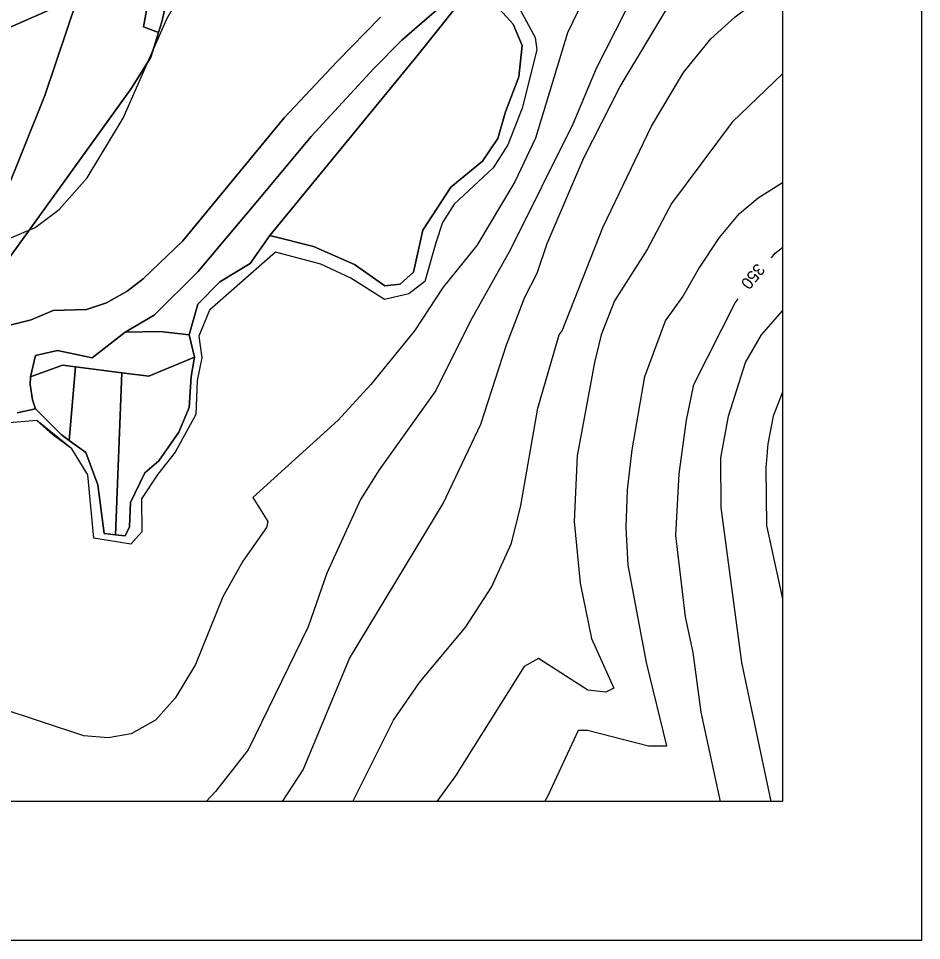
# Model space of a CAD drawing. Extents: x -510989 to -501240, y -1184665 to -1176098.
# Drawn here: x -501694.8 to -501240.2, y -1184460 to -1183995.8 of the extents above; entities that cross this region are included whole.
import ezdxf

# ---------------------------------------------------------------- set-up
doc = ezdxf.new("R2010")
doc.units = 0
for name, color, linetype in [('orna_puda', 7, 'Continuous'), ('ostatni_plocha_x_draha', 7, 'Continuous'), ('popis', 7, 'Continuous'), ('rozpiska', 7, 'Continuous'), ('trvaly_travni_porost', 7, 'Continuous'), ('vodni_plocha_x_vodni_tok_v_koryt_prir_n_upr', 7, 'Continuous'), ('vrstevnice_01', 7, 'Continuous'), ('vrstevnice_02', 7, 'Continuous'), ('vrstevnice_04', 7, 'Continuous')]:
    doc.layers.add(name, color=color, linetype=linetype)

msp = doc.modelspace()

# ---------------------------------------------------------------- linework, layer by layer
at = {"layer": 'orna_puda'}
msp.add_lwpolyline([(-501512.55, -1183995.12), (-501534.61, -1184017.6), (-501561.07, -1184045.86), (-501612.09, -1184107.75), (-501632.04, -1184126.86), (-501640.1, -1184133.08), (-501650.4, -1184138.89), (-501660.56, -1184142.34), (-501677.32, -1184142.83), (-501688.38, -1184147.53), (-501707.95, -1184152.37), (-501728.19, -1184147.52), (-501731.54, -1184150.05), (-501738.69, -1184147.66), (-501728.56, -1184144.08), (-501706.37, -1184125.67), (-501637.9, -1184030.79), (-501628.17, -1184015.32), (-501624.3, -1184002.75), (-501622.66, -1183997.39), (-501612.32, -1183952.6)], dxfattribs=at)
for points in [[(-501612.32, -1183952.6), (-501622.66, -1183997.39), (-501624.3, -1184002.75), (-501631.88, -1183999.91), (-501624.62, -1183960.62), (-501615.08, -1183954.85)], [(-501464.7, -1183977.67), (-501445.71, -1183998.59), (-501441.23, -1184009.29), (-501442.97, -1184025.07), (-501449.69, -1184042.78), (-501453.46, -1184056.27), (-501461.22, -1184067.58), (-501477.17, -1184080.78), (-501491.19, -1184102.41), (-501495.99, -1184123.43), (-501502.72, -1184129.59), (-501510.34, -1184130.29), (-501525.6, -1184119.62), (-501546.27, -1184110.6), (-501568.32, -1184105.06), (-501494.17, -1184014.62)], [(-501664.91, -1183985.01), (-501681.56, -1184034.59), (-501702.32, -1184086.41), (-501722.03, -1184129.14), (-501735.56, -1184129.64), (-501753.3, -1184131.89), (-501747.55, -1184098.48), (-501737.14, -1184058.29), (-501725.5, -1184011.71)], [(-501629.19, -1184175.85), (-501606.21, -1184166.31), (-501607.79, -1184175.98), (-501608.86, -1184191.6), (-501614.12, -1184203.97), (-501624.11, -1184218.42), (-501631.17, -1184224.53), (-501638.45, -1184239.5), (-501638.95, -1184251.68), (-501641.04, -1184256.31), (-501645.92, -1184255.77), (-501642.73, -1184174.11)], [(-501672.55, -1184170.26), (-501666.07, -1184171.1), (-501669.26, -1184208.24), (-501673.38, -1184205.25), (-501686.2, -1184192.28), (-501687.81, -1184187.75), (-501688.92, -1184180.06), (-501688.75, -1184176.23)], [(-501666.07, -1184171.1), (-501642.73, -1184174.11), (-501645.92, -1184255.77), (-501651.57, -1184255.14), (-501654.82, -1184230.52), (-501660.84, -1184214.35), (-501669.26, -1184208.24)]]:
    msp.add_lwpolyline(points, close=True, dxfattribs=at)
at = {"layer": 'ostatni_plocha_x_draha'}
msp.add_lwpolyline([(-501664.91, -1183985.01), (-501725.5, -1184011.71), (-501735.92, -1184015.8), (-501756.19, -1184021.57), (-501777.62, -1184027.66), (-501796.28, -1184026.35), (-501817.33, -1184025.47), (-501837.44, -1184019.49), (-501848.27, -1184040.14), (-501854.1, -1184015.89), (-501894.48, -1184008.62), (-501897.73, -1184020.9), (-501911.35, -1184013.65), (-501926.09, -1183995.79), (-501924.39, -1183992.84)], dxfattribs=at)
at = {"layer": 'popis'}
msp.add_lwpolyline([(-501442.37, -1183991.15), (-501434.74, -1184005.42), (-501433.91, -1184011.62), (-501441.25, -1184040.89), (-501448.43, -1184059.31), (-501455.91, -1184070.91), (-501475.4, -1184089.29), (-501481.35, -1184098.5), (-501484.72, -1184108.73), (-501490.24, -1184128.12), (-501498.31, -1184134.34), (-501510.57, -1184137.27), (-501527.46, -1184126.57), (-501542.53, -1184119.5), (-501565.43, -1184113.46), (-501598.56, -1184142.62), (-501603.96, -1184155.65), (-501602.48, -1184166.68), (-501604.88, -1184178.11), (-501605.58, -1184195.15), (-501615.91, -1184214.08), (-501624.7, -1184225.14), (-501632.88, -1184237.62), (-501632.61, -1184254.22), (-501638.24, -1184260.44), (-501656.8, -1184257.46), (-501659.89, -1184225.51), (-501667.92, -1184212.44), (-501685.55, -1184198.22), (-501705.56, -1184199.8)], dxfattribs=at)
at = {"layer": 'rozpiska'}
for points in [[(-501240.19, -1178160), (-501240.19, -1184460), (-507180.19, -1184460), (-507180.19, -1178160)], [(-507110.19, -1184390), (-507110.19, -1178230), (-501310.19, -1178230), (-501310.19, -1184390)]]:
    msp.add_lwpolyline(points, close=True, dxfattribs=at)
at = {"layer": 'trvaly_travni_porost'}
for points in [[(-501624.62, -1183960.62), (-501631.88, -1183999.91), (-501624.3, -1184002.75), (-501628.17, -1184015.32), (-501637.9, -1184030.79), (-501706.37, -1184125.67), (-501722.03, -1184129.14), (-501702.32, -1184086.41), (-501681.56, -1184034.59), (-501664.91, -1183985.01)], [(-501463.08, -1183970.24), (-501464.7, -1183977.67), (-501494.17, -1184014.62), (-501568.32, -1184105.06), (-501578.13, -1184119.1), (-501593.44, -1184128.39), (-501604.5, -1184139.67), (-501608.91, -1184155.1), (-501623.51, -1184153.4), (-501641.1, -1184153.63), (-501626.41, -1184145.06), (-501604.42, -1184123.24), (-501574.28, -1184087.35), (-501547.37, -1184055.26), (-501515.98, -1184021), (-501501.76, -1184006.63), (-501472.92, -1183981.46)], [(-501623.51, -1184153.4), (-501608.91, -1184155.1), (-501606.21, -1184166.31), (-501629.19, -1184175.85), (-501642.73, -1184174.11), (-501666.07, -1184171.1), (-501672.55, -1184170.26), (-501688.75, -1184176.23), (-501686.24, -1184165.52), (-501675.22, -1184162.88), (-501657.77, -1184166.57), (-501641.1, -1184153.63)]]:
    msp.add_lwpolyline(points, close=True, dxfattribs=at)
at = {"layer": 'vodni_plocha_x_vodni_tok_v_koryt_prir_n_upr'}
for points in [[(-501695.38, -1184194.27), (-501686.2, -1184192.28), (-501673.38, -1184205.25), (-501669.26, -1184208.24), (-501660.84, -1184214.35), (-501654.82, -1184230.52), (-501651.57, -1184255.14), (-501645.92, -1184255.77), (-501641.04, -1184256.31), (-501638.95, -1184251.68), (-501638.45, -1184239.5), (-501631.17, -1184224.53), (-501624.11, -1184218.42), (-501614.12, -1184203.97), (-501608.86, -1184191.6), (-501607.79, -1184175.98), (-501606.21, -1184166.31), (-501608.91, -1184155.1), (-501604.5, -1184139.67), (-501593.44, -1184128.39), (-501578.13, -1184119.1), (-501568.32, -1184105.06), (-501546.27, -1184110.6), (-501525.6, -1184119.62), (-501510.34, -1184130.29), (-501502.72, -1184129.59), (-501495.99, -1184123.43), (-501491.19, -1184102.41), (-501477.17, -1184080.78), (-501461.22, -1184067.58), (-501453.46, -1184056.27), (-501449.69, -1184042.78), (-501442.97, -1184025.07), (-501441.23, -1184009.29), (-501445.71, -1183998.59), (-501464.7, -1183977.67)], [(-501472.92, -1183981.46), (-501501.76, -1184006.63), (-501515.98, -1184021), (-501547.37, -1184055.26), (-501574.28, -1184087.35), (-501604.42, -1184123.24), (-501626.41, -1184145.06), (-501641.1, -1184153.63), (-501657.77, -1184166.57), (-501675.22, -1184162.88), (-501686.24, -1184165.52), (-501688.75, -1184176.23), (-501688.92, -1184180.06), (-501687.81, -1184187.75), (-501686.2, -1184192.28), (-501695.38, -1184194.27)], [(-501707.95, -1184152.37), (-501688.38, -1184147.53), (-501677.32, -1184142.83), (-501660.56, -1184142.34), (-501650.4, -1184138.89), (-501640.1, -1184133.08), (-501632.04, -1184126.86), (-501612.09, -1184107.75), (-501561.07, -1184045.86), (-501534.61, -1184017.6), (-501512.55, -1183995.12)], [(-501442.37, -1183991.15), (-501434.74, -1184005.42), (-501433.91, -1184011.62), (-501441.25, -1184040.89), (-501448.43, -1184059.31), (-501455.91, -1184070.91), (-501475.4, -1184089.29), (-501481.35, -1184098.5), (-501484.72, -1184108.73), (-501490.24, -1184128.12), (-501498.31, -1184134.34), (-501510.57, -1184137.27), (-501527.46, -1184126.57), (-501542.53, -1184119.5), (-501565.43, -1184113.46), (-501598.56, -1184142.62), (-501603.96, -1184155.65), (-501602.48, -1184166.68), (-501604.88, -1184178.11), (-501605.58, -1184195.15), (-501615.91, -1184214.08), (-501624.7, -1184225.14), (-501632.88, -1184237.62), (-501632.61, -1184254.22), (-501638.24, -1184260.44), (-501656.8, -1184257.46), (-501659.89, -1184225.51), (-501667.92, -1184212.44), (-501677.51, -1184205.32), (-501685.55, -1184198.22), (-501705.56, -1184199.8)]]:
    msp.add_lwpolyline(points, dxfattribs=at)
at = {"layer": 'vrstevnice_01'}
for points in [[(-501310.22, -1183824.21), (-501328, -1183858), (-501335.81, -1183868), (-501362.19, -1183893), (-501378.09, -1183914), (-501387.59, -1183930), (-501394.41, -1183944), (-501413, -1183992), (-501418.41, -1184003), (-501434.5, -1184056), (-501444.91, -1184078), (-501464.09, -1184110), (-501481, -1184131), (-501495.41, -1184153), (-501517.41, -1184180), (-501533.81, -1184198), (-501576.81, -1184237), (-501569.19, -1184249), (-501569.91, -1184252), (-501581.91, -1184269), (-501591.91, -1184287)], [(-501428.69, -1184109), (-501410.19, -1184066), (-501391.91, -1184030), (-501362.5, -1183981), (-501353.19, -1183967), (-501336.31, -1183948), (-501327.59, -1183939), (-501310.21, -1183925.9)], [(-501700.69, -1184107), (-501686.31, -1184101), (-501674.31, -1184092), (-501660.19, -1184076), (-501642.09, -1184046), (-501620.19, -1183996), (-501589.31, -1183942)], [(-501310.21, -1184023.59), (-501335.59, -1184048), (-501366.09, -1184089), (-501378.31, -1184112), (-501394.69, -1184138), (-501401.41, -1184155), (-501404.81, -1184169), (-501413.59, -1184216), (-501415, -1184249), (-501412.09, -1184280), (-501406.41, -1184308), (-501395.09, -1184333), (-501399.09, -1184335), (-501408.19, -1184334), (-501433, -1184318), (-501440.31, -1184322), (-501474.81, -1184377), (-501484.27, -1184390)], [(-501561.9, -1184390), (-501551.5, -1184374), (-501528.09, -1184318), (-501481, -1184240), (-501462, -1184200), (-501449.19, -1184160), (-501439.81, -1184136), (-501433.69, -1184124), (-501428.69, -1184109)], [(-501315.68, -1184116.3), (-501313.81, -1184114), (-501310.2, -1184111.06)], [(-501341.41, -1184390), (-501351.09, -1184345), (-501355.09, -1184315), (-501359, -1184297), (-501363.91, -1184256), (-501362.19, -1184225), (-501358.5, -1184198), (-501354.81, -1184180), (-501334.09, -1184139), (-501332.44, -1184136.96)], [(-501310.2, -1184183.89), (-501314.91, -1184196), (-501317.59, -1184210), (-501318.59, -1184222), (-501318.19, -1184251), (-501310.19, -1184287.98)], [(-501591.91, -1184287), (-501605.69, -1184321), (-501615.91, -1184338), (-501625.81, -1184349), (-501638.09, -1184356), (-501649.69, -1184358), (-501661.81, -1184357), (-501704, -1184343)]]:
    msp.add_lwpolyline(points, dxfattribs=at)
at = {"layer": 'vrstevnice_02'}
for points in [[(-501310.21, -1183883.93), (-501334.19, -1183908), (-501360.91, -1183942), (-501375.19, -1183964), (-501404, -1184021), (-501415.69, -1184049), (-501447.19, -1184112), (-501467.31, -1184148), (-501484.69, -1184183), (-501513.19, -1184223), (-501522.69, -1184238), (-501539.5, -1184275), (-501549, -1184302), (-501579.19, -1184364), (-501595.69, -1184385), (-501600.26, -1184390)], [(-501526.5, -1184390), (-501506, -1184349), (-501492.91, -1184330), (-501469.59, -1184302), (-501456.59, -1184282), (-501446.59, -1184260), (-501441.91, -1184241), (-501433.31, -1184192), (-501422.69, -1184155), (-501421.09, -1184153), (-501400.59, -1184101), (-501376.09, -1184050), (-501360.09, -1184023), (-501346.19, -1184006), (-501334, -1183995), (-501319.59, -1183984), (-501310.21, -1183978.25)], [(-501429.87, -1184390), (-501428.09, -1184387), (-501412.81, -1184354), (-501408.31, -1184354), (-501377.59, -1184362), (-501368.41, -1184362), (-501378.69, -1184320), (-501387.81, -1184271), (-501388.81, -1184252), (-501388.19, -1184233), (-501385.91, -1184213), (-501379.5, -1184176), (-501369, -1184148), (-501360.5, -1184136), (-501352.5, -1184122), (-501341.91, -1184106), (-501331.81, -1184094), (-501322.41, -1184086), (-501310.2, -1184078.39)], [(-501315.94, -1184390), (-501330.69, -1184320), (-501341.09, -1184242), (-501341.19, -1184217), (-501337.31, -1184196), (-501328.81, -1184169), (-501320.81, -1184155), (-501310.2, -1184143.03)]]:
    msp.add_lwpolyline(points, dxfattribs=at)

# ---------------------------------------------------------------- texts
at = {"layer": 'vrstevnice_04'}
msp.add_text('350', height=6, rotation=230.4909, dxfattribs=at).set_placement((-501323.09, -1184118.62))

doc.saveas('drawing.dxf')
